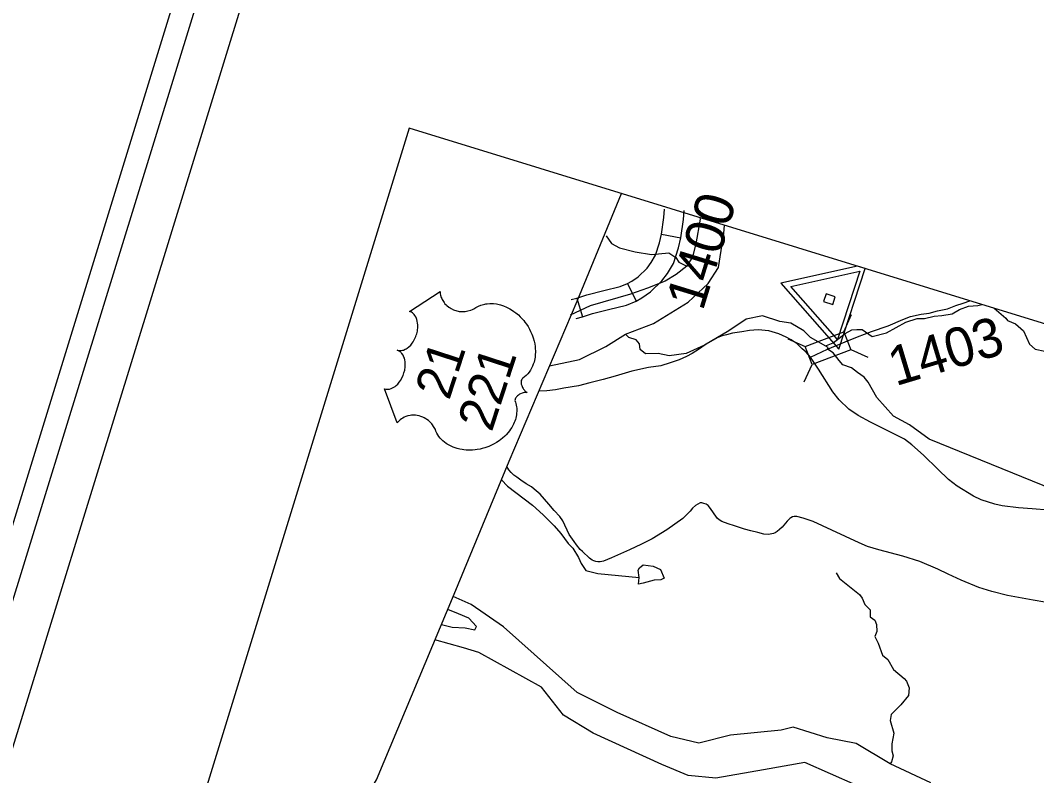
# Model space of a CAD drawing. Extents: x 1347947 to 1350662, y 1027710 to 1030532.
# Drawn here: x 1348130.6 to 1348247.6, y 1029046.3 to 1029133.4 of the extents above; entities that cross this region are included whole.
import ezdxf

# ---------------------------------------------------------------- set-up
doc = ezdxf.new("R2010")
doc.units = 0
for name, color, linetype in [('Default', 7, 'Continuous'), ('Prop Leader Line Light', 7, 'Continuous'), ('Prop WCC CELL', 7, 'Continuous'), ('Sheet Plot Border Inside CELL', 7, 'Continuous'), ('Sheet Title CELL', 7, 'Continuous')]:
    doc.layers.add(name, color=color, linetype=linetype)

msp = doc.modelspace()

# ---------------------------------------------------------------- linework, layer by layer
at = {"layer": 'Default'}
for p, q in [((1348204.4, 1029108.74), (1348206.62, 1029108.32)), ((1348227.83, 1029104.77), (1348226.95, 1029105.04)), ((1348200.47, 1029103.05), (1348201.47, 1029101.03)), ((1348194.66, 1029101.35), (1348195.29, 1029099.19)), ((1348225.4, 1029097.47), (1348226.29, 1029099.46)), ((1348218.96, 1029096.68), (1348220.94, 1029095.78)), ((1348226.18, 1029095.44), (1348228.16, 1029094.55)), ((1348220.84, 1029091.72), (1348221.74, 1029093.7))]:
    msp.add_line(p, q, dxfattribs=at)
for points in [[(1348083.52, 1028822.71), (1348089.97, 1028837.63), (1348104.26, 1028873.21), (1348113.82, 1028899.5), (1348162.49, 1029030.38), (1348171.57, 1029045.86), (1348180.52, 1029067.26), (1348186.85, 1029082.58), (1348194.68, 1029101.03), (1348199.8, 1029113.4)], [(1348194.01, 1029101.19), (1348194.66, 1029101.35), (1348195.82, 1029101.74), (1348197.74, 1029102.25), (1348199.65, 1029102.7), (1348200.47, 1029103.05), (1348200.97, 1029103.33), (1348201.7, 1029103.82), (1348202.73, 1029104.83), (1348203.21, 1029105.46), (1348203.71, 1029106.3), (1348204.17, 1029107.74), (1348204.4, 1029108.74), (1348204.68, 1029110.66), (1348204.74, 1029111.6)], [(1348194.56, 1029099.01), (1348195.29, 1029099.19), (1348196.47, 1029099.59), (1348198.28, 1029100.07), (1348200.36, 1029100.55), (1348201.47, 1029101.03), (1348202.15, 1029101.41), (1348203.12, 1029102.07), (1348204.42, 1029103.34), (1348205.08, 1029104.2), (1348205.78, 1029105.37), (1348206.34, 1029107.14), (1348206.62, 1029108.32), (1348206.92, 1029110.43), (1348206.99, 1029111.47)], [(1348191.51, 1029093.57), (1348194.96, 1029094.29), (1348198, 1029095.78), (1348200.26, 1029097.2), (1348203.49, 1029098.44), (1348207.45, 1029100.9), (1348209.77, 1029103.05), (1348210.97, 1029104.88), (1348211.56, 1029108.79), (1348211.64, 1029109.76)], [(1348208.8, 1029110.63), (1348208.85, 1029110.44), (1348208.35, 1029107.61), (1348207.95, 1029106.12), (1348207.33, 1029105.04), (1348206.09, 1029104.08), (1348204.81, 1029103.3), (1348202.78, 1029102.52), (1348200.84, 1029101.8), (1348196.2, 1029100.47), (1348193.9, 1029099.4)], [(1348198.03, 1029108.52), (1348198.64, 1029107.66), (1348199.55, 1029107.16), (1348201.36, 1029106.69), (1348203.25, 1029106.37), (1348205.26, 1029106.58), (1348206.05, 1029106.04), (1348206.38, 1029105.52), (1348207.33, 1029105.04)], [(1348226.95, 1029105.04), (1348218.13, 1029103.07), (1348224.81, 1029095.49), (1348227.83, 1029104.77)], [(1348223.39, 1029095.92), (1348224.16, 1029096.21), (1348225.54, 1029097.3), (1348226.3, 1029097.71), (1348226.88, 1029097.75), (1348227.49, 1029097.74), (1348228.64, 1029096.95), (1348230.32, 1029097.38), (1348232.54, 1029098.59), (1348233.85, 1029099), (1348234.69, 1029099.01), (1348235.8, 1029099.28), (1348236.69, 1029099.37), (1348237.88, 1029099.57), (1348238.72, 1029100.05), (1348239.73, 1029100.43), (1348240.82, 1029100.5), (1348241.28, 1029100.63)], [(1348223.5, 1029095.48), (1348225.54, 1029096.33), (1348226.96, 1029096.91), (1348228.59, 1029097.5), (1348230.51, 1029098.18), (1348232.17, 1029098.89), (1348233.08, 1029099.24), (1348234.3, 1029099.5), (1348235.21, 1029099.63), (1348236.18, 1029099.9), (1348237.32, 1029100.13), (1348238.29, 1029100.52), (1348239.14, 1029100.8), (1348239.91, 1029101.05)], [(1348223.5, 1029095.48), (1348223.57, 1029095.69), (1348221.54, 1029096.81), (1348220.78, 1029097.59), (1348219.29, 1029098.49), (1348218.04, 1029098.66), (1348216.04, 1029099.31), (1348214.13, 1029098.92), (1348212.15, 1029097.6), (1348209.35, 1029095.95), (1348207.25, 1029094.97), (1348205.29, 1029094.73), (1348204, 1029094.97), (1348202.57, 1029094.96), (1348201.95, 1029095.46), (1348201.86, 1029096.08), (1348201.48, 1029096.56), (1348200.62, 1029096.84), (1348200.26, 1029097.2)], [(1348242.71, 1029100.19), (1348244.04, 1029099.06), (1348244.25, 1029098.79), (1348245.14, 1029098.41), (1348246.07, 1029097.58), (1348246.77, 1029096.07), (1348247.44, 1029095.47), (1348249.63, 1029095.03), (1348250.92, 1029094.92), (1348253.1, 1029095.18), (1348254.14, 1029095.39), (1348256.24, 1029095.67), (1348257.13, 1029095.6), (1348257.75, 1029095.45), (1348258.83, 1029094.48), (1348259.65, 1029094.19), (1348260.46, 1029094.35), (1348260.76, 1029094.63)], [(1348221.56, 1029094.55), (1348221.04, 1029095.13), (1348220.59, 1029095.53), (1348220, 1029096.09), (1348219.32, 1029096.56), (1348218.75, 1029096.86), (1348217.91, 1029097.26), (1348216.74, 1029097.58), (1348215.54, 1029097.7), (1348214.54, 1029097.64), (1348213.65, 1029097.49), (1348212.58, 1029097.33), (1348211.9, 1029097.15), (1348211.4, 1029097.01), (1348210.82, 1029096.78), (1348209.53, 1029096.06), (1348208.66, 1029095.45), (1348207.93, 1029094.99), (1348207.28, 1029094.65), (1348206.42, 1029094.27), (1348205.4, 1029093.92), (1348204.31, 1029093.58), (1348202.92, 1029093.36), (1348200.99, 1029092.96), (1348199.07, 1029092.37), (1348197.68, 1029091.98), (1348196.15, 1029091.62), (1348194.83, 1029091.26), (1348193.14, 1029091), (1348192.19, 1029090.78), (1348191.18, 1029090.68), (1348190.27, 1029090.65)], [(1348221.56, 1029094.55), (1348223.5, 1029095.48)], [(1348248.96, 1029076.95), (1348247.07, 1029077.09), (1348245.52, 1029077.21), (1348243.61, 1029077.44), (1348242.76, 1029077.61), (1348241.2, 1029078.12), (1348240.31, 1029078.54), (1348238.45, 1029079.7), (1348237.46, 1029080.48), (1348236.2, 1029081.67), (1348234.58, 1029083.27), (1348233.23, 1029084.46), (1348232.37, 1029085.11), (1348230.83, 1029085.88), (1348228.48, 1029087.09), (1348227.04, 1029087.83), (1348225.96, 1029088.57), (1348224.86, 1029089.63), (1348224.14, 1029090.55), (1348222.49, 1029093.16), (1348221.56, 1029094.55)], [(1348225.26, 1029093.68), (1348224.84, 1029094.16), (1348224.17, 1029095.06), (1348223.5, 1029095.48)], [(1348258.77, 1029076.95), (1348255.58, 1029077.61), (1348251.65, 1029078.7), (1348250.06, 1029078.83), (1348248.33, 1029079.78), (1348235.22, 1029085.11), (1348232.96, 1029086.77), (1348231.1, 1029087.77), (1348229.2, 1029089.92), (1348228.18, 1029091.68), (1348227.74, 1029092.26), (1348226.96, 1029092.79), (1348226.26, 1029093.32), (1348225.26, 1029093.68)], [(1348248.53, 1029066.34), (1348247.2, 1029066.57), (1348244.25, 1029067.11), (1348242.43, 1029067.56), (1348240.92, 1029068.03), (1348238.91, 1029068.87), (1348237.39, 1029069.56), (1348236.23, 1029070.12), (1348234.15, 1029071.01), (1348232.17, 1029071.64), (1348229.41, 1029072.38), (1348228.11, 1029072.75), (1348227.17, 1029073.16), (1348224.02, 1029074.64), (1348221.88, 1029075.63), (1348220.72, 1029076.03), (1348219.97, 1029076.21), (1348219.69, 1029076.2), (1348219.5, 1029076.17), (1348219.3, 1029076.07), (1348219.17, 1029075.99), (1348218.86, 1029075.68), (1348218.31, 1029074.97), (1348218, 1029074.71), (1348217.71, 1029074.48), (1348217.47, 1029074.34), (1348217.29, 1029074.26), (1348216.7, 1029074.15), (1348216.17, 1029074.18), (1348215.5, 1029074.36), (1348214.7, 1029074.56), (1348213.95, 1029074.75), (1348212.81, 1029075.14), (1348212.06, 1029075.37), (1348211.33, 1029075.64), (1348211.03, 1029075.82), (1348210.82, 1029076.03), (1348210.3, 1029076.76), (1348209.93, 1029077.27), (1348209.76, 1029077.48), (1348209.53, 1029077.62), (1348209.28, 1029077.71), (1348209.04, 1029077.78), (1348208.84, 1029077.78), (1348208.32, 1029077.47), (1348207.95, 1029077.15), (1348207.7, 1029076.83), (1348206.85, 1029075.98), (1348205.95, 1029075.33), (1348205, 1029074.68), (1348203.33, 1029073.62), (1348202.11, 1029073), (1348200.7, 1029072.38), (1348198.66, 1029071.44), (1348197.71, 1029071.07), (1348197.32, 1029070.99), (1348197.08, 1029070.97), (1348196.84, 1029071.01), (1348196.6, 1029071.11), (1348196.42, 1029071.19), (1348196.09, 1029071.4), (1348195.32, 1029072.19), (1348195.05, 1029072.42), (1348194.62, 1029072.94), (1348194.34, 1029073.31), (1348193.77, 1029074.12), (1348193.05, 1029075.69), (1348192.7, 1029076.21), (1348192.04, 1029076.89), (1348191.41, 1029077.61), (1348190.41, 1029078.76), (1348189.73, 1029079.35), (1348189.42, 1029079.61), (1348188.82, 1029079.95), (1348188.19, 1029080.41), (1348187.74, 1029080.75), (1348187.39, 1029080.98), (1348187.08, 1029081.29), (1348186.82, 1029081.6), (1348186.6, 1029081.98)], [(1348185.96, 1029080.42), (1348186.67, 1029079.71), (1348189.55, 1029077.5), (1348190.79, 1029076.39), (1348192.05, 1029075.14), (1348192.8, 1029074.26), (1348193.67, 1029073.08), (1348194.2, 1029072.54), (1348194.85, 1029071.5), (1348195.15, 1029070.78), (1348195.69, 1029069.98), (1348197.05, 1029069.63), (1348201.81, 1029069.19)], [(1348201.81, 1029069.19), (1348201.7, 1029070.04), (1348201.85, 1029070.29), (1348202.27, 1029070.62), (1348203.45, 1029070.49), (1348204.29, 1029070.09), (1348204.7, 1029069.09), (1348204.33, 1029068.92), (1348203.56, 1029068.88), (1348202.29, 1029068.51), (1348201.74, 1029068.4), (1348201.81, 1029069.19)], [(1348224.5, 1029069.73), (1348224.88, 1029069.08), (1348227.19, 1029067.23), (1348227.49, 1029066.8), (1348227.81, 1029066.08), (1348228.44, 1029065.45), (1348228.41, 1029065.06), (1348228.44, 1029064.63), (1348228.96, 1029064.25), (1348229.16, 1029063.77), (1348229.18, 1029062.95), (1348228.98, 1029062.39), (1348229.36, 1029061.6), (1348229.86, 1029060.24), (1348230.44, 1029059.74), (1348231.12, 1029058.58), (1348232.32, 1029057.55), (1348232.59, 1029057.25), (1348232.92, 1029056.46), (1348232.82, 1029055.58), (1348231.97, 1029054.51), (1348230.86, 1029053.41), (1348230.71, 1029052.71), (1348231.16, 1029051.26), (1348230.93, 1029050.02), (1348230.9, 1029049.22), (1348231.06, 1029048.65), (1348230.87, 1029047.96), (1348230.73, 1029047.7)], [(1348235.39, 1029045.54), (1348230.73, 1029047.7), (1348226.82, 1029050.04), (1348223.46, 1029050.71), (1348219.57, 1029051.92), (1348218.19, 1029051.6), (1348212.34, 1029051.01), (1348208.71, 1029050.11), (1348205.46, 1029050.87), (1348199.3, 1029053.64), (1348194.68, 1029055.92), (1348186.19, 1029063.5), (1348182.47, 1029066.08), (1348180.4, 1029066.97)], [(1348179.06, 1029063.78), (1348180.28, 1029063.46), (1348181.8, 1029063.38), (1348182.91, 1029063.14), (1348183.11, 1029063.55), (1348182.22, 1029064.5), (1348181.02, 1029065.01), (1348179.79, 1029065.51)], [(1348229.78, 1029043.96), (1348220.92, 1029047.85), (1348216.16, 1029047.02), (1348210.67, 1029046.07), (1348207.47, 1029046.36), (1348204.45, 1029047.65), (1348196.53, 1029051.25), (1348193.1, 1029053.3), (1348190.59, 1029056.56), (1348183.38, 1029060.53), (1348181.59, 1029061.07), (1348178.31, 1029061.98)]]:
    msp.add_lwpolyline(points, dxfattribs=at)
for points in [[(1348227.24, 1029104.47), (1348224.67, 1029096.58), (1348219.29, 1029102.69)], [(1348172.52, 1029090.92), (1348172.65, 1029090.89), (1348172.81, 1029090.87), (1348172.9, 1029090.87), (1348173.07, 1029090.89), (1348173.29, 1029090.95), (1348173.52, 1029091.06), (1348173.73, 1029091.19), (1348173.85, 1029091.29), (1348174.03, 1029091.46), (1348174.21, 1029091.67), (1348174.38, 1029091.92), (1348174.52, 1029092.17), (1348174.65, 1029092.46), (1348174.75, 1029092.75), (1348174.83, 1029093.08), (1348174.88, 1029093.46), (1348174.89, 1029093.63), (1348174.89, 1029093.84), (1348174.87, 1029094.03), (1348174.84, 1029094.25), (1348174.79, 1029094.43), (1348174.74, 1029094.57), (1348174.64, 1029094.79), (1348174.52, 1029094.97), (1348174.44, 1029095.06), (1348174.37, 1029095.13), (1348174.2, 1029095.26), (1348174.13, 1029095.3), (1348173.96, 1029095.37), (1348174.11, 1029095.34), (1348174.2, 1029095.32), (1348174.3, 1029095.32), (1348174.4, 1029095.32), (1348174.56, 1029095.35), (1348174.69, 1029095.38), (1348174.9, 1029095.47), (1348175.01, 1029095.53), (1348175.1, 1029095.59), (1348175.31, 1029095.75), (1348175.52, 1029095.96), (1348175.61, 1029096.06), (1348175.7, 1029096.17), (1348175.8, 1029096.31), (1348175.89, 1029096.47), (1348175.97, 1029096.62), (1348176.05, 1029096.78), (1348176.11, 1029096.94), (1348176.16, 1029097.08), (1348176.21, 1029097.25), (1348176.26, 1029097.41), (1348176.29, 1029097.57), (1348176.32, 1029097.76), (1348176.33, 1029097.91), (1348176.34, 1029098.11), (1348176.34, 1029098.3), (1348176.32, 1029098.47), (1348176.28, 1029098.7), (1348176.24, 1029098.89), (1348176.18, 1029099.03), (1348176.1, 1029099.21), (1348176, 1029099.38), (1348175.91, 1029099.49), (1348175.82, 1029099.58), (1348175.72, 1029099.67), (1348175.6, 1029099.74), (1348175.5, 1029099.79), (1348175.4, 1029099.83), (1348178.9, 1029102.13), (1348178.9, 1029102.05), (1348178.93, 1029101.85), (1348178.96, 1029101.69), (1348179.04, 1029101.43), (1348179.1, 1029101.31), (1348179.15, 1029101.19), (1348179.22, 1029101.07), (1348179.28, 1029100.97), (1348179.38, 1029100.84), (1348179.47, 1029100.72), (1348179.59, 1029100.6), (1348179.69, 1029100.5), (1348179.91, 1029100.32), (1348180.05, 1029100.23), (1348180.17, 1029100.15), (1348180.44, 1029100.02), (1348180.57, 1029099.97), (1348180.7, 1029099.93), (1348180.84, 1029099.89), (1348180.98, 1029099.86), (1348181.12, 1029099.84), (1348181.25, 1029099.82), (1348181.41, 1029099.81), (1348181.6, 1029099.81), (1348181.79, 1029099.83), (1348182.11, 1029099.88), (1348182.44, 1029099.97), (1348182.64, 1029100.05), (1348182.81, 1029100.14), (1348183.04, 1029100.28), (1348183.16, 1029100.35), (1348183.32, 1029100.43), (1348183.61, 1029100.55), (1348183.74, 1029100.6), (1348183.89, 1029100.64), (1348184.04, 1029100.67), (1348184.19, 1029100.7), (1348184.33, 1029100.72), (1348184.63, 1029100.75), (1348184.91, 1029100.74), (1348185.06, 1029100.74), (1348185.39, 1029100.69), (1348185.54, 1029100.67), (1348185.85, 1029100.59), (1348186.21, 1029100.48), (1348186.54, 1029100.34), (1348186.92, 1029100.14), (1348187.14, 1029100.01), (1348187.39, 1029099.84), (1348187.61, 1029099.68), (1348187.92, 1029099.43), (1348188.13, 1029099.22), (1348188.38, 1029098.95), (1348188.53, 1029098.78), (1348188.68, 1029098.59), (1348188.85, 1029098.35), (1348189.03, 1029098.08), (1348189.2, 1029097.77), (1348189.33, 1029097.53), (1348189.47, 1029097.21), (1348189.54, 1029097.03), (1348189.63, 1029096.77), (1348189.73, 1029096.42), (1348189.8, 1029096.08), (1348189.85, 1029095.8), (1348189.87, 1029095.56), (1348189.88, 1029095.25), (1348189.86, 1029094.75), (1348189.84, 1029094.57), (1348189.81, 1029094.36), (1348189.76, 1029094.17), (1348189.72, 1029093.99), (1348189.64, 1029093.74), (1348189.54, 1029093.51), (1348189.43, 1029093.29), (1348189.31, 1029093.07), (1348189.15, 1029092.85), (1348188.99, 1029092.65), (1348188.8, 1029092.46), (1348188.44, 1029092.15), (1348188.34, 1029092.06), (1348188.3, 1029092), (1348188.25, 1029091.86), (1348188.23, 1029091.71), (1348188.24, 1029091.55), (1348188.26, 1029091.45), (1348188.3, 1029091.31), (1348188.34, 1029091.19), (1348188.41, 1029091.06), (1348188.47, 1029090.95), (1348188.51, 1029090.88), (1348188.65, 1029090.71), (1348188.72, 1029090.65), (1348188.81, 1029090.57), (1348188.95, 1029090.49), (1348188.74, 1029090.5), (1348188.6, 1029090.49), (1348188.46, 1029090.46), (1348188.34, 1029090.42), (1348188.18, 1029090.35), (1348188.06, 1029090.28), (1348187.92, 1029090.2), (1348187.81, 1029090.1), (1348187.72, 1029090.01), (1348187.66, 1029089.93), (1348187.6, 1029089.83), (1348187.56, 1029089.74), (1348187.54, 1029089.67), (1348187.53, 1029089.55), (1348187.58, 1029089.38), (1348187.63, 1029089.22), (1348187.67, 1029089.04), (1348187.71, 1029088.84), (1348187.73, 1029088.69), (1348187.73, 1029088.52), (1348187.74, 1029088.33), (1348187.72, 1029088.12), (1348187.7, 1029087.91), (1348187.67, 1029087.73), (1348187.63, 1029087.54), (1348187.58, 1029087.37), (1348187.52, 1029087.2), (1348187.45, 1029087.04), (1348187.37, 1029086.85), (1348187.26, 1029086.63), (1348187.16, 1029086.45), (1348187.03, 1029086.26), (1348186.9, 1029086.07), (1348186.74, 1029085.87), (1348186.52, 1029085.63), (1348186.36, 1029085.47), (1348186.08, 1029085.22), (1348185.71, 1029084.93), (1348185.4, 1029084.73), (1348185.15, 1029084.59), (1348184.75, 1029084.39), (1348184.5, 1029084.28), (1348184.06, 1029084.13), (1348183.74, 1029084.03), (1348183.52, 1029083.98), (1348183.16, 1029083.91), (1348182.95, 1029083.89), (1348182.63, 1029083.86), (1348182.35, 1029083.85), (1348182.09, 1029083.85), (1348181.92, 1029083.86), (1348181.63, 1029083.88), (1348181.43, 1029083.91), (1348181.16, 1029083.96), (1348180.88, 1029084.03), (1348180.63, 1029084.11), (1348180.42, 1029084.18), (1348180.19, 1029084.29), (1348179.94, 1029084.41), (1348179.73, 1029084.53), (1348179.59, 1029084.63), (1348179.41, 1029084.76), (1348179.23, 1029084.92), (1348179.06, 1029085.09), (1348178.92, 1029085.24), (1348178.77, 1029085.42), (1348178.66, 1029085.6), (1348178.54, 1029085.81), (1348178.43, 1029086.03), (1348178.36, 1029086.22), (1348178.24, 1029086.46), (1348178.16, 1029086.59), (1348178.05, 1029086.75), (1348177.94, 1029086.88), (1348177.84, 1029086.99), (1348177.69, 1029087.15), (1348177.57, 1029087.25), (1348177.39, 1029087.39), (1348177.25, 1029087.47), (1348177.08, 1029087.57), (1348176.9, 1029087.65), (1348176.69, 1029087.73), (1348176.5, 1029087.79), (1348176.28, 1029087.83), (1348176.06, 1029087.86), (1348175.86, 1029087.87), (1348175.63, 1029087.86), (1348175.46, 1029087.84), (1348175.21, 1029087.79), (1348174.98, 1029087.72), (1348174.78, 1029087.63), (1348174.6, 1029087.54), (1348174.45, 1029087.44), (1348174.32, 1029087.34), (1348174.18, 1029087.21), (1348174.05, 1029087.09), (1348173.98, 1029087)], [(1348224.39, 1029101.52), (1348223.36, 1029101.86), (1348223.07, 1029100.97), (1348224.11, 1029100.64)], [(1348220.94, 1029095.78), (1348225.4, 1029097.48), (1348226.19, 1029095.4), (1348221.74, 1029093.7)]]:
    msp.add_lwpolyline(points, close=True, dxfattribs=at)
at = {"layer": 'Prop WCC CELL'}
for p, q in [((1348175.36, 1029120.93), (1348067.18, 1028769.65)), ((1348393.41, 1029053.78), (1348175.36, 1029120.93))]:
    msp.add_line(p, q, dxfattribs=at)
at = {"layer": 'Sheet Plot Border Inside CELL'}
msp.add_lwpolyline([(1348980.53, 1028253.25), (1349471, 1029845.94), (1348462.64, 1030156.47), (1347972.16, 1028563.78)], close=True, dxfattribs=at)
at = {"layer": 'Sheet Title CELL'}
for points in [[(1348458.46, 1030134.23), (1348022.85, 1028719.76)], [(1348461.76, 1030127.97), (1348043.83, 1028770.87)]]:
    msp.add_lwpolyline(points, dxfattribs=at)

# ---------------------------------------------------------------- texts
at = {"layer": 'Default'}
for s, p in [('21', (1348179.95, 1029089.5)), ('221', (1348184.85, 1029085.84))]:
    msp.add_text(s, height=4.232, rotation=71.9667, dxfattribs=at).set_placement(p)
at = {"layer": 'Prop Leader Line Light'}
for s, rotation, p in [('1400', 72.8834, (1348209.14, 1029099.78)), ('1403', 16.7695, (1348231.34, 1029091.2))]:
    msp.add_text(s, height=4.5, rotation=rotation, dxfattribs=at).set_placement(p)

doc.saveas('drawing.dxf')
